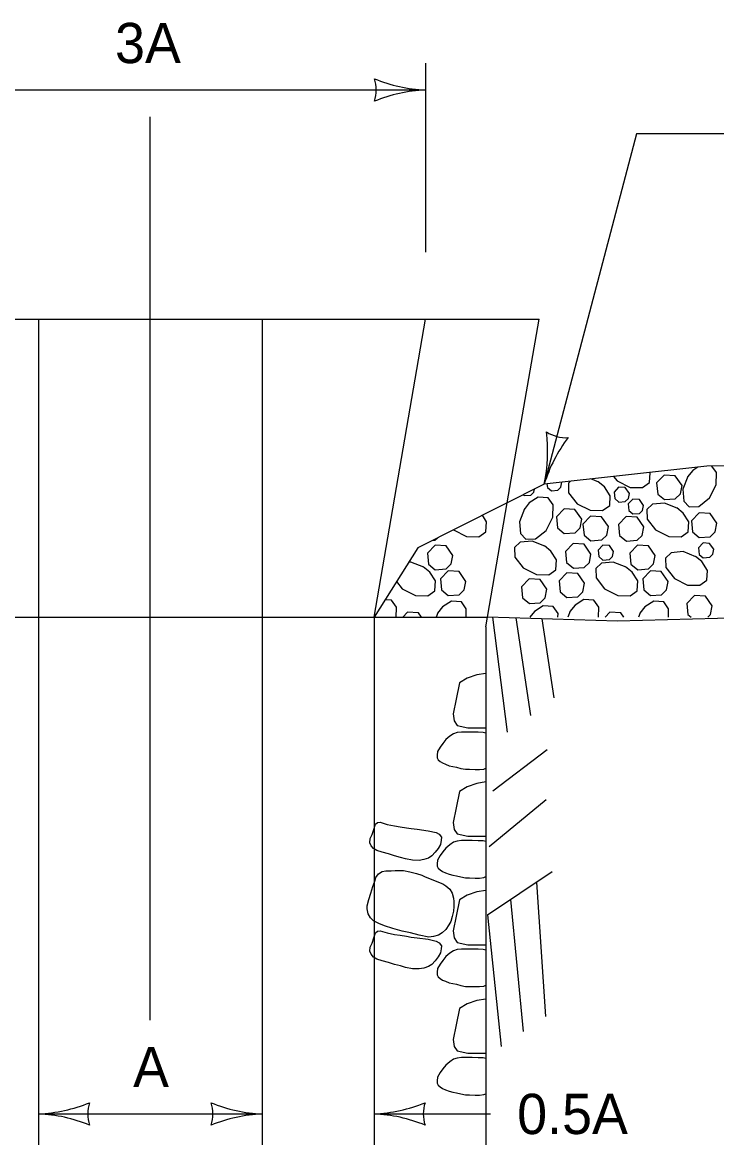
# Model space of a CAD drawing. Extents: x 49991.4 to 50021, y 49987.6 to 50011.4.
# Drawn here: x 50001.108 to 50002.143, y 49996.429 to 49998.093 of the extents above; entities that cross this region are included whole.
import ezdxf

# ---------------------------------------------------------------- set-up
doc = ezdxf.new("R2010")
doc.units = 0
for name, color, linetype in [('Level 1', 7, 'Continuous'), ('Level 2', 7, 'Continuous'), ('Level 3', 7, 'Continuous'), ('Level 6', 7, 'Continuous')]:
    doc.layers.add(name, color=color, linetype=linetype)

msp = doc.modelspace()

# ---------------------------------------------------------------- linework, layer by layer
at = {"layer": 'Level 1'}
for p, q in [((50000.7101, 49997.6503), (50001.8786, 49997.6503)), ((50000.8807, 49997.6503), (50001.7091, 49997.6503)), ((50001.1324, 49997.6503), (50001.1324, 49994.0392)), ((50001.4658, 49997.6503), (50001.4658, 49994.0392)), ((50001.6325, 49997.2058), (50001.7094, 49997.6503)), ((50001.8312, 49997.3765), (50001.8786, 49997.6503)), ((50001.9127, 49997.407), (50001.9126, 49997.4071)), ((50001.9674, 49997.4073), (50001.9558, 49997.4119)), ((50001.7992, 49997.1915), (50001.8312, 49997.3765)), ((50000.9657, 49997.2058), (50001.6325, 49997.2058)), ((50001.6325, 49997.2058), (50001.8017, 49997.2058)), ((50001.6325, 49997.2058), (50001.6325, 49994.0392)), ((50001.7276, 49997.2123), (50001.725, 49997.2058)), ((50001.8093, 49997.2056), (50001.8311, 49997.0343)), ((50001.8437, 49997.2046), (50001.8657, 49997.0592)), ((50001.8826, 49997.2034), (50001.9005, 49997.0856)), ((50001.925, 49997.2148), (50001.9214, 49997.2058)), ((50002.0291, 49997.2123), (50002.0265, 49997.2058)), ((50001.7992, 49997.1915), (50001.7992, 49994.0392)), ((50001.8094, 49996.9466), (50001.8905, 49997.0086)), ((50001.8042, 49996.8636), (50001.8889, 49996.9338)), ((50001.8017, 49996.762), (50001.898, 49996.8266)), ((50001.8745, 49996.8108), (50001.8883, 49996.6101)), ((50001.8358, 49996.7849), (50001.8546, 49996.588)), ((50001.8017, 49996.762), (50001.822, 49996.5657))]:
    msp.add_line(p, q, dxfattribs=at)
for points in [[(50002.7593, 49997.443), (50002.44, 49997.4327), (50002.1288, 49997.431), (50001.8863, 49997.4042), (50001.6977, 49997.3093), (50001.6325, 49997.2058)], [(50001.9896, 49997.4156), (50001.9947, 49997.4092), (50002.0143, 49997.3993), (50002.0328, 49997.399), (50002.0432, 49997.4064), (50002.0442, 49997.4212), (50002.0439, 49997.4216)], [(50002.0917, 49997.4022), (50002.0814, 49997.4167), (50002.0651, 49997.4177), (50002.0537, 49997.4059), (50002.0554, 49997.3894), (50002.0655, 49997.381), (50002.0816, 49997.3821), (50002.0892, 49997.3895), (50002.0917, 49997.4022)], [(50002.1004, 49997.4157), (50002.0928, 49997.3965), (50002.0943, 49997.3789), (50002.1023, 49997.3705), (50002.1166, 49997.3708), (50002.1328, 49997.3835), (50002.1426, 49997.4031), (50002.1429, 49997.4216), (50002.1362, 49997.4311)], [(50002.1154, 49997.4295), (50002.1076, 49997.4246), (50002.0999, 49997.4149)], [(50001.8903, 49997.4047), (50001.8909, 49997.3993), (50001.8969, 49997.3943), (50001.9066, 49997.395), (50001.9112, 49997.3994), (50001.9126, 49997.407)], [(50001.9255, 49997.4086), (50001.9222, 49997.4054), (50001.9225, 49997.3912), (50001.9352, 49997.3749), (50001.9548, 49997.3651), (50001.9733, 49997.3648), (50001.9838, 49997.3722), (50001.9847, 49997.3869), (50001.9763, 49997.4001), (50001.9666, 49997.4078)], [(50001.8568, 49997.3673), (50001.8492, 49997.3481), (50001.8507, 49997.3305), (50001.8587, 49997.3222), (50001.873, 49997.3224), (50001.8892, 49997.3351), (50001.899, 49997.3548), (50001.8993, 49997.3733), (50001.8919, 49997.3837), (50001.8772, 49997.3847), (50001.864, 49997.3762), (50001.8563, 49997.3665)], [(50001.8549, 49997.3884), (50001.8566, 49997.3871), (50001.8662, 49997.3878), (50001.8708, 49997.3922), (50001.8717, 49997.3969)], [(50002.0131, 49997.3902), (50002.0069, 49997.399), (50001.9971, 49997.3995), (50001.9903, 49997.3924), (50001.9913, 49997.3825), (50001.9973, 49997.3775), (50002.007, 49997.3782), (50002.0116, 49997.3826), (50002.0131, 49997.3902)], [(50002.0342, 49997.3724), (50002.028, 49997.3812), (50002.0182, 49997.3817), (50002.0114, 49997.3747), (50002.0124, 49997.3648), (50002.0185, 49997.3597), (50002.0282, 49997.3604), (50002.0327, 49997.3648), (50002.0342, 49997.3724)], [(50002.0845, 49997.3683), (50002.0653, 49997.3759), (50002.0477, 49997.3744), (50002.0394, 49997.3664), (50002.0396, 49997.3521), (50002.0523, 49997.3359), (50002.072, 49997.3261), (50002.0905, 49997.3257), (50002.1009, 49997.3331), (50002.1019, 49997.3479), (50002.0934, 49997.361), (50002.0837, 49997.3688)], [(50001.7507, 49997.336), (50001.7508, 49997.3359), (50001.7704, 49997.3261), (50001.7889, 49997.3257), (50001.7993, 49997.3331), (50001.8003, 49997.3479), (50001.794, 49997.3577)], [(50001.9423, 49997.3517), (50001.932, 49997.3663), (50001.9157, 49997.3672), (50001.9043, 49997.3554), (50001.906, 49997.3389), (50001.9161, 49997.3305), (50001.9322, 49997.3317), (50001.9398, 49997.339), (50001.9423, 49997.3517)], [(50001.982, 49997.341), (50001.9718, 49997.3556), (50001.9554, 49997.3565), (50001.944, 49997.3447), (50001.9457, 49997.3282), (50001.9558, 49997.3198), (50001.972, 49997.321), (50001.9795, 49997.3283), (50001.982, 49997.341)], [(50002.0349, 49997.3404), (50002.0246, 49997.355), (50002.0083, 49997.3559), (50001.9969, 49997.3441), (50001.9986, 49997.3276), (50002.0087, 49997.3192), (50002.0248, 49997.3204), (50002.0324, 49997.3277), (50002.0349, 49997.3404)], [(50002.1436, 49997.3458), (50002.1334, 49997.3604), (50002.117, 49997.3613), (50002.1056, 49997.3495), (50002.1073, 49997.333), (50002.1174, 49997.3246), (50002.1335, 49997.3258), (50002.1411, 49997.3331), (50002.1436, 49997.3458)], [(50001.7192, 49997.3201), (50001.7233, 49997.3204), (50001.727, 49997.324)], [(50001.8872, 49997.3116), (50001.868, 49997.3192), (50001.8504, 49997.3177), (50001.8421, 49997.3097), (50001.8423, 49997.2954), (50001.855, 49997.2792), (50001.8746, 49997.2694), (50001.8931, 49997.2691), (50001.9036, 49997.2765), (50001.9045, 49997.2912), (50001.8961, 49997.3044), (50001.8864, 49997.3121)], [(50001.7501, 49997.2977), (50001.7399, 49997.3123), (50001.7235, 49997.3132), (50001.7122, 49997.3014), (50001.7138, 49997.2849), (50001.7239, 49997.2765), (50001.7401, 49997.2777), (50001.7477, 49997.2851), (50001.7501, 49997.2977)], [(50001.9559, 49997.2999), (50001.9457, 49997.3145), (50001.9293, 49997.3155), (50001.918, 49997.3037), (50001.9196, 49997.2871), (50001.9297, 49997.2787), (50001.9459, 49997.2799), (50001.9535, 49997.2873), (50001.9559, 49997.2999)], [(50001.9895, 49997.3037), (50001.9834, 49997.3125), (50001.9736, 49997.313), (50001.9667, 49997.3059), (50001.9677, 49997.296), (50001.9738, 49997.291), (50001.9835, 49997.2917), (50001.988, 49997.2961), (50001.9895, 49997.3037)], [(50002.0517, 49997.2977), (50002.0414, 49997.3123), (50002.0251, 49997.3132), (50002.0137, 49997.3014), (50002.0154, 49997.2849), (50002.0255, 49997.2765), (50002.0416, 49997.2777), (50002.0492, 49997.2851), (50002.0517, 49997.2977)], [(50002.1124, 49997.2959), (50002.0932, 49997.3035), (50002.0756, 49997.3019), (50002.0672, 49997.294), (50002.0675, 49997.2797), (50002.0802, 49997.2635), (50002.0998, 49997.2536), (50002.1183, 49997.2533), (50002.1287, 49997.2607), (50002.1297, 49997.2755), (50002.1213, 49997.2886), (50002.1116, 49997.2964)], [(50002.1389, 49997.3071), (50002.1328, 49997.3158), (50002.123, 49997.3164), (50002.1162, 49997.3093), (50002.1171, 49997.2994), (50002.1232, 49997.2944), (50002.1329, 49997.2951), (50002.1374, 49997.2995), (50002.1389, 49997.3071)], [(50001.7067, 49997.2804), (50001.6875, 49997.288), (50001.6841, 49997.2877)], [(50002.0083, 49997.2804), (50001.9891, 49997.288), (50001.9715, 49997.2864), (50001.9631, 49997.2785), (50001.9634, 49997.2642), (50001.9761, 49997.248), (50001.9957, 49997.2382), (50002.0142, 49997.2378), (50002.0246, 49997.2452), (50002.0256, 49997.26), (50002.0172, 49997.2731), (50002.0075, 49997.2809)], [(50001.666, 49997.2589), (50001.6745, 49997.248), (50001.6942, 49997.2382), (50001.7127, 49997.2378), (50001.7231, 49997.2452), (50001.7241, 49997.26), (50001.7156, 49997.2731), (50001.7059, 49997.2809)], [(50001.7694, 49997.2592), (50001.7592, 49997.2737), (50001.7428, 49997.2747), (50001.7314, 49997.2629), (50001.7331, 49997.2464), (50001.7432, 49997.238), (50001.7593, 49997.2391), (50001.7669, 49997.2465), (50001.7694, 49997.2592)], [(50001.9463, 49997.2563), (50001.9361, 49997.2709), (50001.9197, 49997.2718), (50001.9083, 49997.26), (50001.91, 49997.2435), (50001.9201, 49997.2351), (50001.9362, 49997.2363), (50001.9438, 49997.2436), (50001.9463, 49997.2563)], [(50002.071, 49997.2592), (50002.0607, 49997.2737), (50002.0444, 49997.2747), (50002.033, 49997.2629), (50002.0346, 49997.2464), (50002.0447, 49997.238), (50002.0609, 49997.2391), (50002.0685, 49997.2465), (50002.071, 49997.2592)], [(50001.8903, 49997.2474), (50001.88, 49997.262), (50001.8637, 49997.2629), (50001.8523, 49997.2511), (50001.854, 49997.2346), (50001.8641, 49997.2262), (50001.8802, 49997.2273), (50001.8878, 49997.2347), (50001.8903, 49997.2474)], [(50002.1367, 49997.2226), (50002.1264, 49997.2372), (50002.1101, 49997.2381), (50002.0987, 49997.2263), (50002.1003, 49997.2098), (50002.1051, 49997.2058)], [(50001.6657, 49997.2053), (50001.666, 49997.2207), (50001.6586, 49997.2312), (50001.6489, 49997.2318)], [(50001.7699, 49997.2058), (50001.7701, 49997.2183), (50001.7627, 49997.2287), (50001.748, 49997.2297), (50001.7348, 49997.2212), (50001.7271, 49997.2115)], [(50001.9067, 49997.2058), (50001.9068, 49997.2114), (50001.8994, 49997.2219), (50001.8846, 49997.2228), (50001.8715, 49997.2144), (50001.8646, 49997.2058)], [(50001.9673, 49997.2058), (50001.9675, 49997.2207), (50001.9601, 49997.2312), (50001.9454, 49997.2321), (50001.9322, 49997.2237), (50001.9245, 49997.214)], [(50002.0714, 49997.2058), (50002.0717, 49997.2183), (50002.0643, 49997.2287), (50002.0495, 49997.2297), (50002.0363, 49997.2212), (50002.0286, 49997.2115)], [(50002.1299, 49997.2058), (50002.1342, 49997.2099), (50002.1367, 49997.2226)], [(50001.7035, 49997.2058), (50001.6989, 49997.2124), (50001.6825, 49997.2133), (50001.6753, 49997.2058)], [(50002.7221, 49997.2058), (50002.5639, 49997.2008), (50002.5131, 49997.2058), (50002.3839, 49997.2058), (50002.3004, 49997.2079), (50002.2188, 49997.2058), (50001.9955, 49997.2), (50001.8017, 49997.2058)], [(50002.0051, 49997.2058), (50002.0005, 49997.2124), (50001.9841, 49997.2133), (50001.9769, 49997.2058)], [(50001.7992, 49997.1218), (50001.7857, 49997.1197), (50001.7714, 49997.1147), (50001.76, 49997.1078), (50001.7552, 49997.0834), (50001.7507, 49997.0614), (50001.7522, 49997.0511), (50001.7566, 49997.0444), (50001.7724, 49997.0408), (50001.7992, 49997.0408)], [(50001.7992, 49997.0329), (50001.7952, 49997.034), (50001.788, 49997.0342), (50001.7789, 49997.0344), (50001.7698, 49997.0344), (50001.7629, 49997.0344), (50001.7565, 49997.0337), (50001.7509, 49997.0319), (50001.7457, 49997.0281), (50001.7398, 49997.0232), (50001.7349, 49997.0176), (50001.7309, 49997.012), (50001.7272, 49997.0053), (50001.7265, 49996.9999), (50001.7265, 49996.9961), (50001.728, 49996.9932), (50001.7312, 49996.9907), (50001.7346, 49996.9883), (50001.7393, 49996.9865), (50001.7447, 49996.9842), (50001.7501, 49996.9829), (50001.7555, 49996.982), (50001.7619, 49996.9802), (50001.7691, 49996.9789), (50001.775, 49996.9789), (50001.7834, 49996.9784), (50001.7895, 49996.9784), (50001.7962, 49996.9793), (50001.7992, 49996.9806)], [(50001.7992, 49996.96), (50001.7857, 49996.9578), (50001.7714, 49996.9529), (50001.76, 49996.946), (50001.7552, 49996.9216), (50001.7507, 49996.8996), (50001.7522, 49996.8893), (50001.7566, 49996.8826), (50001.7724, 49996.879), (50001.7992, 49996.879)], [(50001.7992, 49996.871), (50001.7952, 49996.8721), (50001.788, 49996.8723), (50001.7789, 49996.8726), (50001.7698, 49996.8726), (50001.7629, 49996.8726), (50001.7565, 49996.8719), (50001.7509, 49996.8701), (50001.7457, 49996.8663), (50001.7398, 49996.8614), (50001.7349, 49996.8558), (50001.7309, 49996.8502), (50001.7272, 49996.8435), (50001.7265, 49996.8381), (50001.7265, 49996.8343), (50001.728, 49996.8314), (50001.7312, 49996.8289), (50001.7346, 49996.8264), (50001.7393, 49996.8246), (50001.7447, 49996.8224), (50001.7501, 49996.8211), (50001.7555, 49996.8202), (50001.7619, 49996.8184), (50001.7691, 49996.817), (50001.775, 49996.817), (50001.7834, 49996.8166), (50001.7895, 49996.8166), (50001.7962, 49996.8175), (50001.7992, 49996.8188)], [(50001.7992, 49996.7982), (50001.7857, 49996.796), (50001.7714, 49996.7911), (50001.76, 49996.7841), (50001.7552, 49996.7597), (50001.7507, 49996.7378), (50001.7522, 49996.7275), (50001.7566, 49996.7208), (50001.7724, 49996.7172), (50001.7992, 49996.7172)], [(50001.7992, 49996.7092), (50001.7952, 49996.7103), (50001.788, 49996.7105), (50001.7789, 49996.7107), (50001.7698, 49996.7107), (50001.7629, 49996.7107), (50001.7565, 49996.7101), (50001.7509, 49996.7083), (50001.7457, 49996.7045), (50001.7398, 49996.6995), (50001.7349, 49996.6939), (50001.7309, 49996.6883), (50001.7272, 49996.6816), (50001.7265, 49996.6762), (50001.7265, 49996.6724), (50001.728, 49996.6695), (50001.7312, 49996.6671), (50001.7346, 49996.6646), (50001.7393, 49996.6628), (50001.7447, 49996.6606), (50001.7501, 49996.6592), (50001.7555, 49996.6583), (50001.7619, 49996.6565), (50001.7691, 49996.6552), (50001.775, 49996.6552), (50001.7834, 49996.6548), (50001.7895, 49996.6548), (50001.7962, 49996.6556), (50001.7992, 49996.6569)], [(50001.7992, 49996.6363), (50001.7857, 49996.6342), (50001.7714, 49996.6292), (50001.76, 49996.6223), (50001.7552, 49996.5979), (50001.7507, 49996.5759), (50001.7522, 49996.5656), (50001.7566, 49996.5589), (50001.7724, 49996.5553), (50001.7992, 49996.5553)], [(50001.7992, 49996.5474), (50001.7952, 49996.5484), (50001.788, 49996.5487), (50001.7789, 49996.5489), (50001.7698, 49996.5489), (50001.7629, 49996.5489), (50001.7565, 49996.5482), (50001.7509, 49996.5464), (50001.7457, 49996.5426), (50001.7398, 49996.5377), (50001.7349, 49996.5321), (50001.7309, 49996.5265), (50001.7272, 49996.5198), (50001.7265, 49996.5144), (50001.7265, 49996.5106), (50001.728, 49996.5077), (50001.7312, 49996.5052), (50001.7346, 49996.5028), (50001.7393, 49996.501), (50001.7447, 49996.4987), (50001.7501, 49996.4974), (50001.7555, 49996.4965), (50001.7619, 49996.4947), (50001.7691, 49996.4934), (50001.775, 49996.4934), (50001.7834, 49996.4929), (50001.7895, 49996.4929), (50001.7962, 49996.4938), (50001.7992, 49996.4951)]]:
    msp.add_lwpolyline(points, dxfattribs=at)
for points in [[(50001.6349, 49996.8969), (50001.6379, 49996.8994), (50001.6416, 49996.8999), (50001.6521, 49996.8967), (50001.663, 49996.8945), (50001.6713, 49996.8931), (50001.6807, 49996.8918), (50001.6881, 49996.8904), (50001.697, 49996.8896), (50001.713, 49996.8873), (50001.7253, 49996.8846), (50001.7297, 49996.8819), (50001.7331, 49996.8775), (50001.7327, 49996.873), (50001.7314, 49996.8669), (50001.7282, 49996.8609), (50001.7238, 49996.8551), (50001.7189, 49996.8497), (50001.7139, 49996.8466), (50001.7066, 49996.8443), (50001.6997, 49996.843), (50001.6898, 49996.8432), (50001.6792, 49996.8452), (50001.6721, 49996.8475), (50001.663, 49996.8497), (50001.6539, 49996.8528), (50001.6448, 49996.8551), (50001.6369, 49996.8578), (50001.6317, 49996.8607), (50001.6283, 49996.8649), (50001.6265, 49996.8694), (50001.627, 49996.8757), (50001.6297, 49996.8815), (50001.6322, 49996.8893)], [(50001.6499, 49996.8274), (50001.6583, 49996.8276), (50001.6642, 49996.8282), (50001.6767, 49996.828), (50001.6859, 49996.8262), (50001.6957, 49996.8235), (50001.7036, 49996.8209), (50001.709, 49996.8186), (50001.7179, 49996.815), (50001.7262, 49996.8115), (50001.7349, 49996.8083), (50001.7398, 49996.805), (50001.7457, 49996.8003), (50001.7491, 49996.794), (50001.7511, 49996.7866), (50001.7516, 49996.7817), (50001.7513, 49996.7745), (50001.7509, 49996.7673), (50001.7489, 49996.7595), (50001.7472, 49996.7519), (50001.7442, 49996.747), (50001.7395, 49996.7402), (50001.7339, 49996.7351), (50001.7287, 49996.7315), (50001.7213, 49996.7293), (50001.7142, 49996.7286), (50001.6996, 49996.7315), (50001.6871, 49996.7349), (50001.6745, 49996.7373), (50001.6607, 49996.7416), (50001.6482, 49996.7454), (50001.6398, 49996.7488), (50001.6319, 49996.753), (50001.6275, 49996.7573), (50001.6236, 49996.7633), (50001.6223, 49996.7707), (50001.6223, 49996.7754), (50001.6248, 49996.7846), (50001.628, 49996.7942), (50001.6309, 49996.8041), (50001.6339, 49996.8123), (50001.6354, 49996.8177), (50001.6393, 49996.8229), (50001.6447, 49996.8267)], [(50001.6349, 49996.7351), (50001.6379, 49996.7376), (50001.6416, 49996.738), (50001.6521, 49996.7349), (50001.663, 49996.7326), (50001.6713, 49996.7313), (50001.6807, 49996.73), (50001.6881, 49996.7286), (50001.697, 49996.7277), (50001.713, 49996.7255), (50001.7253, 49996.7228), (50001.7297, 49996.7201), (50001.7331, 49996.7156), (50001.7327, 49996.7111), (50001.7314, 49996.7051), (50001.7282, 49996.6991), (50001.7238, 49996.6932), (50001.7189, 49996.6879), (50001.7139, 49996.6847), (50001.7066, 49996.6825), (50001.6997, 49996.6811), (50001.6898, 49996.6814), (50001.6792, 49996.6834), (50001.6721, 49996.6856), (50001.663, 49996.6879), (50001.6539, 49996.691), (50001.6448, 49996.6932), (50001.6369, 49996.6959), (50001.6317, 49996.6988), (50001.6283, 49996.7031), (50001.6265, 49996.7076), (50001.627, 49996.7138), (50001.6297, 49996.7197), (50001.6322, 49996.7275)]]:
    msp.add_lwpolyline(points, close=True, dxfattribs=at)
at = {"layer": 'Level 3'}
for p, q in [((50001.7091, 49998.032), (50001.7091, 49997.7503)), ((50000.8807, 49997.992), (50001.7091, 49997.992)), ((50001.1324, 49996.4649), (50001.4658, 49996.4649)), ((50001.6325, 49996.4649), (50001.8059, 49996.4649))]:
    msp.add_line(p, q, dxfattribs=at)
msp.add_lwpolyline([(50002.2045, 49997.9266), (50002.0238, 49997.9266), (50001.8863, 49997.4042)], dxfattribs=at)
for centre, radius, start, end in [((50001.7183, 49998.2141), 0.2223, 247.456, 267.6395), ((50001.5809, 49997.992), 0.0548, 342.1388, 17.8612), ((50001.7206, 49997.7593), 0.233, 92.8273, 112.0772), ((50001.6583, 49997.4524), 0.233, 348.0835, 7.3333), ((50002.0988, 49997.3389), 0.2223, 142.7122, 162.8957), ((50001.9189, 49997.5282), 0.0548, 237.395, 273.1173), ((50001.121, 49996.6976), 0.233, 272.8273, 292.0772), ((50001.2607, 49996.4649), 0.0548, 162.1388, 197.8612), ((50001.475, 49996.687), 0.2223, 247.456, 267.6395), ((50001.3376, 49996.4649), 0.0548, 342.1388, 17.8612), ((50001.6211, 49996.6976), 0.233, 272.8273, 292.0772), ((50001.7608, 49996.4649), 0.0548, 162.1388, 197.8612), ((50001.1233, 49996.2428), 0.2223, 67.456, 87.6395), ((50001.4773, 49996.2322), 0.233, 92.8273, 112.0772), ((50001.6234, 49996.2428), 0.2223, 67.456, 87.6395)]:
    msp.add_arc(centre, radius, start, end, dxfattribs=at)
at = {"layer": 'Level 6'}
msp.add_line((50001.2991, 49996.6049), (50001.2991, 49997.952), dxfattribs=at)

# ---------------------------------------------------------------- texts
at = {"layer": 'Level 2'}
for s, p in [('3A', (50001.2465, 49998.032)), ('A', (50001.2734, 49996.5049)), ('0.5A', (50001.8459, 49996.4349))]:
    msp.add_text(s, height=0.06, dxfattribs=at).set_placement(p)

doc.saveas('drawing.dxf')
